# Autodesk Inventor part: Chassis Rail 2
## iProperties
Shininess: 20.0
Angle Display Precision: 2
Document Length Units: 11269
Document Angle Units: 11279
Document Time Units: 11290
Document Mass Units: 11283
Document Length Units Precision: 3
Document Angle Units Precision: 2
Compacted: True
Created: 2001-08
Part Number: Chassis Rail 2
Document SubType Name: Modeling
Designer: Martin Budgell
Density: 0.0
Volumn: 0.0
Area: 0.0
PropertySet Name: Model Information
Control State: 0
Master: False
Checked Out: False
Author: Martin Budgell
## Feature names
1. Sweep1
2. Extrusion1
3. Extrusion2
4. Extrusion3
5. Fillet3
6. Sweep2
7. Extrusion4
8. Fillet4
9. Extrusion5
10. Sweep4
11. Fillet5
12. Extrusion6
13. Fillet6
14. Extrusion7
15. Fillet7
16. Extrusion8
17. Fillet8
18. Extrusion9
19. Fillet9
20. Mirror1
21. Extrusion13
22. Fillet13
23. Sweep7
24. Extrusion14
25. Fillet14
26. Sweep8
27. Fillet15
28. Fillet16
29. Extrusion15
30. Extrusion16
31. Extrusion17
32. Extrusion18
33. Extrusion19
34. Fillet17
35. Extrusion20
36. Extrusion21
37. Fillet18
38. Fillet19
39. Extrusion22
40. Extrusion23
41. Hole3
42. Extrusion24
43. Extrusion25
44. Fillet20
45. Hole4
46. Fillet22
47. Extrusion26
48. Extrusion27
49. Extrusion28
50. Fillet24
51. Fillet25
52. Mirror2
53. Fillet26
54. Hole5
55. Extrusion29
56. Mirror4
57. Extrusion30
58. Extrusion31
59. Mirror5
60. Fillet27
61. Fillet28
62. Fillet29
63. Extrusion32
64. Extrusion33
65. Fillet31
66. Extrusion34
67. Hole6
68. Extrusion35
69. Fillet33
70. Extrusion36
71. Mirror6
72. Fillet34
73. Fillet35
74. Hole7
75. Hole8
76. Hole9
77. Extrusion37
78. Fillet36
79. Fillet37
80. Mirror7
81. Fillet38
82. Hole10
83. Extrusion38
84. Extrusion39
85. Fillet40
86. Mirror8
87. Fillet41
88. Extrusion40
89. Fillet42
90. Extrusion42
91. Extrusion43
92. Extrusion44
93. Fillet43
94. Chamfer2
95. Chamfer3
96. Fillet44
97. Fillet46
98. Fillet47
99. Extrusion45
100. Extrusion46
101. Extrusion47
102. Extrusion48
103. Fillet53
104. Fillet54
105. Fillet55
106. Fillet56
107. Fillet57
108. Fillet58
109. Hole11
110. Extrusion49
111. Fillet59
112. Extrusion50
113. Fillet60
114. Fillet61
115. Extrusion51
116. Extrusion52
117. Hole12
118. Hole13
